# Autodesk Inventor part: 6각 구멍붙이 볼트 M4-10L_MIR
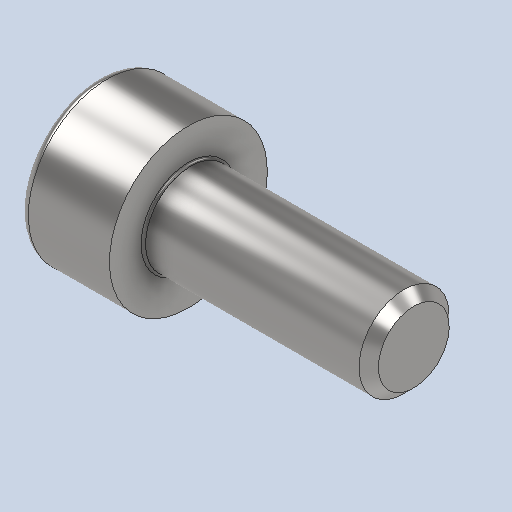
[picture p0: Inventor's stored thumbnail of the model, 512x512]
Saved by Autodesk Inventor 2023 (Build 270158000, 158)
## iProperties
Created: 2025-04
Part Number: 6각 구멍붙이 볼트 M4-10L_MIR
Material: 강철, 연강
Description: 6각머리 태핑 나사
Document SubType Name: Modeling
Designer: Admin
Mass: 2.0371 g
Surface Area: 3.0572 cm^2
Volume: 0.259174 cm^3
Density: 7.86 g/cm^3
Appearance: 기본값
Author: jhkim
Revision Number: 1
Sending System: Autodesk Inventor 2026
Preprocessor: ST-DEVELOPER v20.1
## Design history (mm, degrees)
derived "6각 구멍붙이 볼트 M4-10L.ipt"
feature "솔리드1::6각 구멍붙이 볼트 M4-10L.ipt" dims "d0" = 10
tag "피쳐 태그1"
node "솔리드1"
